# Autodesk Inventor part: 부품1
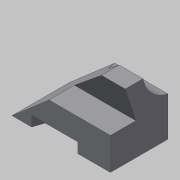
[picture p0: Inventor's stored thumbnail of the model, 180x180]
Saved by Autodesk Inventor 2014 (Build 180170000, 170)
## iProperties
Created: 2015-04
Part Number: 부품1
Material: Generic
Document SubType Name: Modeling
Designer: 203-06
Density: 1 g/cm^3
Appearance: Default
Author: 203-06
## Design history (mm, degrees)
sketch "스케치2"
  geometry: L1 (0, 0)-(-135, 0); L2 (-135, 0)-(-135, 89); L3 (-135, 89)-(-102.383, 89); L4 (-102.383, 89)-(0, 0)
  constraints: 8 end point, 1 horizontal, 1 parallel, 1 perpendicular
  dimensions: "d0" = 135 distance of L1.start L1.end; "d1" = 89 distance of L1.end L2.end; "d2" = 139 deg angle of L1 L4
extrude "돌출1" new body sketch "스케치2" distance "d3" = 79; taper "d4" = 0 deg
sketch "스케치3"
  geometry: L1 (0, 0)-(0, 79) reference; L2 (27, 0)-(52.669, 79); L3 (52.669, 79)-(115.756, 79); L4 (115.756, 79)-(90.088, 0); L5 (27, 0)-(90.088, 0)
  constraints: 8 end point, 2 parallel, 1 horizontal alignment, 1 perpendicular
  dimensions: "d5" = 27 distance from line of L1 L2.start; "d6" = 72 deg angle of L4 L3; "d7" = 60 distance between parallel lines of L4 L2; "d8" = 79 distance between parallel lines of L5 L3
extrude "돌출2" cut sketch "스케치3" distance "d9" = 14; taper "d10" = 0 deg
sketch "스케치4"
  geometry: L1 (0, 79)-(89, 79) reference; L2 (0, 0)-(0, 79) reference; C1 r 44 at (-8, 88)
  constraints: 1 centre point
  dimensions: "d11" = 44 radius of C1; "d12" = 9 distance from line of L1 C1.centre; "d13" = 8 distance from line of C1.centre L2
extrude "돌출3" cut sketch "스케치4" stored distance "d14" = 14; taper "d15" = 0 deg
sketch "스케치5"
  geometry: L1 (0, 0)-(0, 44.733) reference; L2 (89, 0)-(0, 0) reference; L3 (89, 0)-(89, 79) reference; L4 (45, 35)-(0, 20.379); L5 (45, 35)-(45, 0)
  constraints: 4 end point, 2 point on line, 1 perpendicular
  dimensions: "d17" = 44 distance between parallel lines of L5 L3; "d18" = 72 deg angle of L4 L5; "d19" = 35 distance of L4.start L5.end
extrude "돌출4" cut sketch "스케치5" stored distance "d20" = 14; taper "d21" = 0 deg
node "솔리드1"
